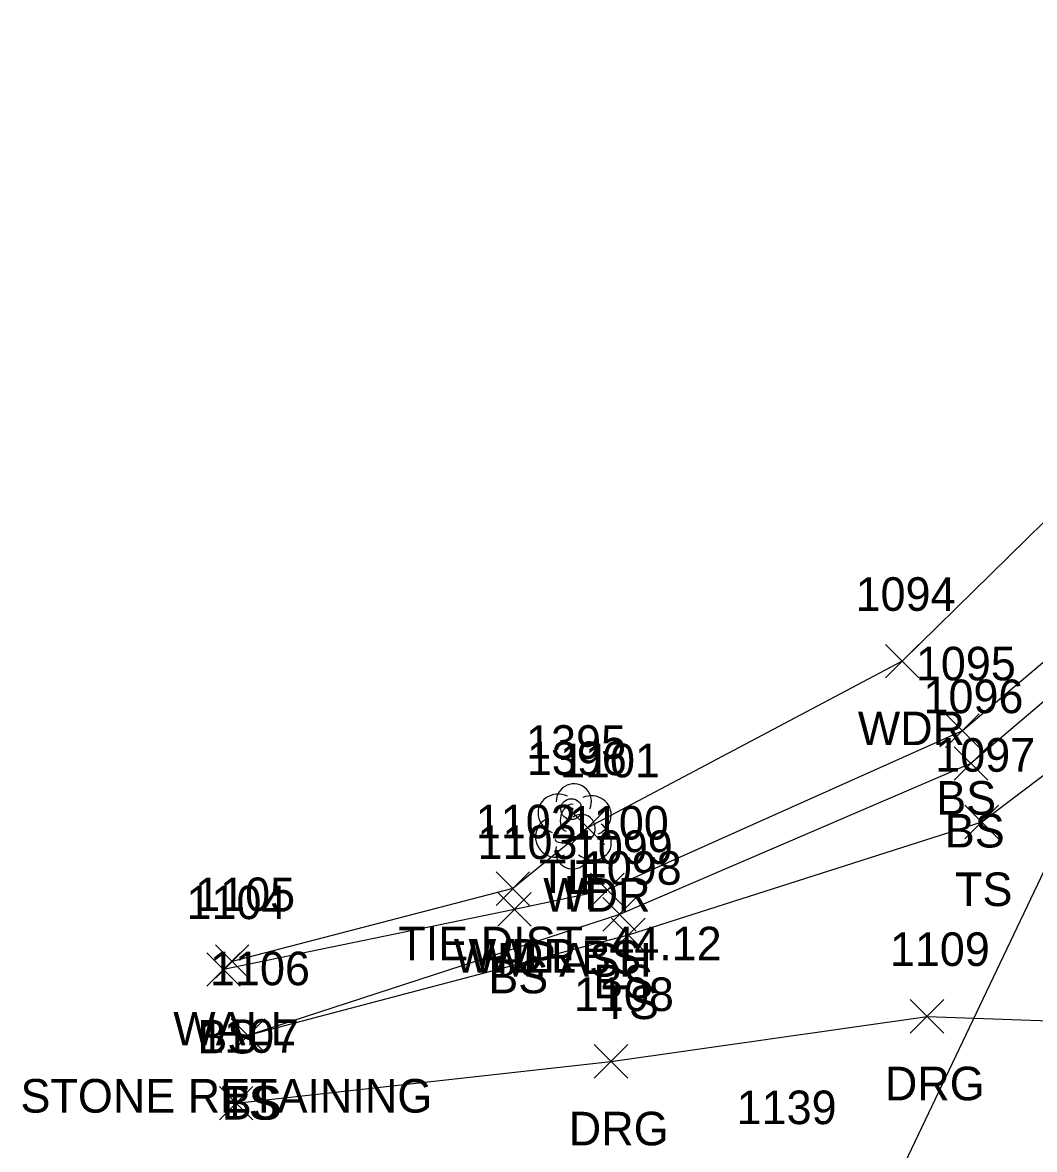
# Model space of a CAD drawing. Extents: x 1599840 to 1601211, y 518904 to 521989.
# Drawn here: x 1600754.8 to 1600815.1, y 521353.5 to 521420.6 of the extents above; entities that cross this region are included whole.
import ezdxf

# ---------------------------------------------------------------- set-up
doc = ezdxf.new("R2010")
doc.units = 0
for name, color, linetype in [('C_A', 7, 'Continuous'), ('C_C', 7, 'Continuous'), ('C_I', 7, 'Continuous'), ('CBP', 7, 'Continuous'), ('DCP', 7, 'Continuous'), ('L_A', 7, 'Continuous'), ('L_C', 7, 'Continuous'), ('L_I', 7, 'Continuous'), ('L_TIC', 7, 'Continuous'), ('LAWA', 7, 'Continuous'), ('LELB', 7, 'Continuous'), ('LTD', 7, 'Continuous'), ('LW', 7, 'Continuous'), ('R_A', 7, 'Continuous'), ('R_I', 7, 'Continuous'), ('R_TIC', 7, 'Continuous'), ('RDG', 7, 'Continuous')]:
    doc.layers.add(name, color=color, linetype=linetype)

msp = doc.modelspace()

# ---------------------------------------------------------------- linework, layer by layer
at = {"layer": 'CBP'}
for radius in [0.625, 0.0833]:
    msp.add_circle((1600787.514, 521373.742), radius, dxfattribs=at)
at = {"layer": 'DCP'}
msp.add_lwpolyline([(1600822.553, 521384.532), (1600796.227, 521329.266)], dxfattribs=at)
at = {"layer": 'L_TIC'}
for points in [[(1600806.213, 521381.554), (1600808.213, 521383.554)], [(1600808.213, 521381.554), (1600806.213, 521383.554)], [(1600809.802, 521377.413), (1600811.802, 521379.413)], [(1600811.802, 521377.413), (1600809.802, 521379.413)], [(1600810.311, 521375.459), (1600812.311, 521377.459)], [(1600812.311, 521375.459), (1600810.311, 521377.459)], [(1600787.481, 521371.639), (1600789.481, 521373.639)], [(1600789.481, 521371.639), (1600787.481, 521373.639)], [(1600810.956, 521371.971), (1600812.956, 521373.971)], [(1600812.956, 521371.971), (1600810.956, 521373.971)], [(1600783.029, 521368.008), (1600785.029, 521370.008)], [(1600785.029, 521368.008), (1600783.029, 521370.008)], [(1600783.029, 521368.008), (1600785.029, 521370.008)], [(1600785.029, 521368.008), (1600783.029, 521370.008)], [(1600788.658, 521367.932), (1600790.658, 521369.932)], [(1600790.658, 521367.932), (1600788.658, 521369.932)], [(1600783.13, 521366.774), (1600785.13, 521368.774)], [(1600785.13, 521366.774), (1600783.13, 521368.774)], [(1600789.382, 521366.475), (1600791.382, 521368.475)], [(1600791.382, 521366.475), (1600789.382, 521368.475)], [(1600789.906, 521365.24), (1600791.906, 521367.24)], [(1600791.906, 521365.24), (1600789.906, 521367.24)], [(1600766.32, 521363.67), (1600768.32, 521365.67)], [(1600768.32, 521363.67), (1600766.32, 521365.67)], [(1600765.803, 521363.192), (1600767.803, 521365.192)], [(1600767.803, 521363.192), (1600765.803, 521365.192)], [(1600767.259, 521359.253), (1600769.259, 521361.253)], [(1600769.259, 521359.253), (1600767.259, 521361.253)], [(1600767.259, 521359.253), (1600769.259, 521361.253)], [(1600769.259, 521359.253), (1600767.259, 521361.253)]]:
    msp.add_lwpolyline(points, dxfattribs=at)
at = {"layer": 'LAWA'}
msp.add_lwpolyline([(1600854.869, 521420.592), (1600857.866, 521409.294), (1600833.295, 521392.861), (1600817.811, 521392.965), (1600807.213, 521382.554), (1600788.481, 521372.639), (1600784.029, 521369.008)], dxfattribs=at)
at = {"layer": 'LELB'}
for points in [[(1600871.885, 521396.639), (1600855.883, 521388.451), (1600839.079, 521382.129), (1600829.586, 521381.436), (1600826.528, 521382.724), (1600821.146, 521379.907), (1600811.956, 521372.971), (1600790.906, 521366.24), (1600768.259, 521360.253)], [(1600821.218, 521384.888), (1600820.512, 521386.628), (1600810.802, 521378.413), (1600789.658, 521368.932), (1600784.13, 521367.774), (1600766.803, 521364.192)], [(1600821.218, 521384.888), (1600811.311, 521376.459), (1600790.382, 521367.475), (1600768.259, 521360.253)]]:
    msp.add_lwpolyline(points, dxfattribs=at)
at = {"layer": 'LTD'}
msp.add_line((1600787.616, 521372.769), (1600787.616, 521372.769), dxfattribs=at)
msp.add_line((1600787.616, 521372.769), (1600787.616, 521372.769), dxfattribs=at)
msp.add_arc((1600787.662, 521374.203), 1.047, 335.52715, 180.95627, dxfattribs=at)
for centre, major_axis, ratio, start_param, end_param in [((1600786.824, 521373.435), (1.21, -0.512), 0.895232, 1.570796, 4.712389), ((1600788.657, 521373.352), (-1.141, -0.483), 0.949671, 1.570796, 4.712389), ((1600787.407, 521373.227), (-0.208, -0.792), 0.645439, 3.141593, 6.283185), ((1600786.533, 521372.06), (0.584, -1.042), 0.959034, 3.141593, 6.283185), ((1600788.116, 521372.602), (-0.5, 0.667), 0.989748, 3.141593, 6.283185), ((1600788.616, 521371.936), (-1.09, 0.792), 0.841452, 1.570796, 4.712389), ((1600787.158, 521372.019), (-0.625, -0.083), 0.423636, 0, 3.141593), ((1600787.616, 521371.269), (0.265, 1.061), 0.942809, 1.570796, 4.712389)]:
    msp.add_ellipse(centre, major_axis=major_axis, ratio=ratio, start_param=start_param, end_param=end_param, dxfattribs=at)
at = {"layer": 'LW'}
msp.add_lwpolyline([(1600784.029, 521369.008), (1600767.32, 521364.67)], dxfattribs=at)
at = {"layer": 'R_TIC'}
for points in [[(1600807.695, 521360.402), (1600809.695, 521362.402)], [(1600809.695, 521360.402), (1600807.695, 521362.402)], [(1600788.875, 521357.718), (1600790.875, 521359.718)], [(1600790.875, 521357.718), (1600788.875, 521359.718)], [(1600766.555, 521355.23), (1600768.555, 521357.23)], [(1600768.555, 521355.23), (1600766.555, 521357.23)]]:
    msp.add_lwpolyline(points, dxfattribs=at)
at = {"layer": 'RDG'}
msp.add_lwpolyline([(1600767.555, 521356.23), (1600789.875, 521358.718), (1600808.695, 521361.402), (1600833.35, 521360.525), (1600845.915, 521365.131), (1600857.247, 521366.665)], dxfattribs=at)

# ---------------------------------------------------------------- texts
at = {"layer": 'C_A'}
msp.add_text('TIE', height=2, dxfattribs=at).set_placement((1600785.593, 521368.742))
at = {"layer": 'C_C'}
msp.add_text('TIE DIST=44.12', height=2, dxfattribs=at).set_placement((1600777.215, 521364.742))
at = {"layer": 'C_I'}
msp.add_text('1395', height=2, dxfattribs=at).set_placement((1600784.821, 521376.742))
at = {"layer": 'L_A'}
for s, p in [('WDR', (1600804.575, 521377.554)), ('BS', (1600809.243, 521373.413)), ('BS', (1600809.752, 521371.459)), ('WDR', (1600785.843, 521367.639)), ('H', (1600787.049, 521367.769)), ('TS', (1600810.365, 521367.971)), ('WALL', (1600780.517, 521364.008)), ('WDR', (1600781.391, 521364.008)), ('BS', (1600788.099, 521363.932)), ('BS', (1600782.571, 521362.774)), ('BS', (1600788.823, 521362.475)), ('TS', (1600789.316, 521361.24)), ('WALL', (1600763.808, 521359.67)), ('BS', (1600765.244, 521359.192)), ('TS', (1600766.669, 521355.253)), ('BS', (1600766.7, 521355.253))]:
    msp.add_text(s, height=2, dxfattribs=at).set_placement(p)
at = {"layer": 'L_C'}
for s, p in [('M. ASH', (1600783.08, 521363.769)), ('STONE RETAINING', (1600754.714, 521355.67))]:
    msp.add_text(s, height=2, dxfattribs=at).set_placement(p)
at = {"layer": 'L_I'}
for s, p in [('1094', (1600804.442, 521385.554)), ('1095', (1600808.031, 521381.413)), ('1096', (1600808.484, 521379.459)), ('1396', (1600784.868, 521375.769)), ('1101', (1600786.843, 521375.639)), ('1097', (1600809.184, 521375.971)), ('1102', (1600781.825, 521372.008)), ('1102', (1600781.825, 521372.008)), ('1100', (1600787.367, 521371.932)), ('1103', (1600781.926, 521370.774)), ('1099', (1600787.603, 521370.475)), ('1098', (1600788.135, 521369.24)), ('1105', (1600765.115, 521367.67)), ('1104', (1600764.598, 521367.192)), ('1106', (1600766, 521363.253)), ('1106', (1600766, 521363.253))]:
    msp.add_text(s, height=2, dxfattribs=at).set_placement(p)
at = {"layer": 'R_A'}
for p in [(1600806.183, 521356.402), (1600787.363, 521353.718)]:
    msp.add_text('DRG', height=2, dxfattribs=at).set_placement(p)
at = {"layer": 'R_I'}
for s, p in [('1109', (1600806.483, 521364.402)), ('1108', (1600787.671, 521361.718)), ('1107', (1600765.351, 521359.23)), ('1139', (1600797.36, 521354.982))]:
    msp.add_text(s, height=2, dxfattribs=at).set_placement(p)

doc.saveas('drawing.dxf')
